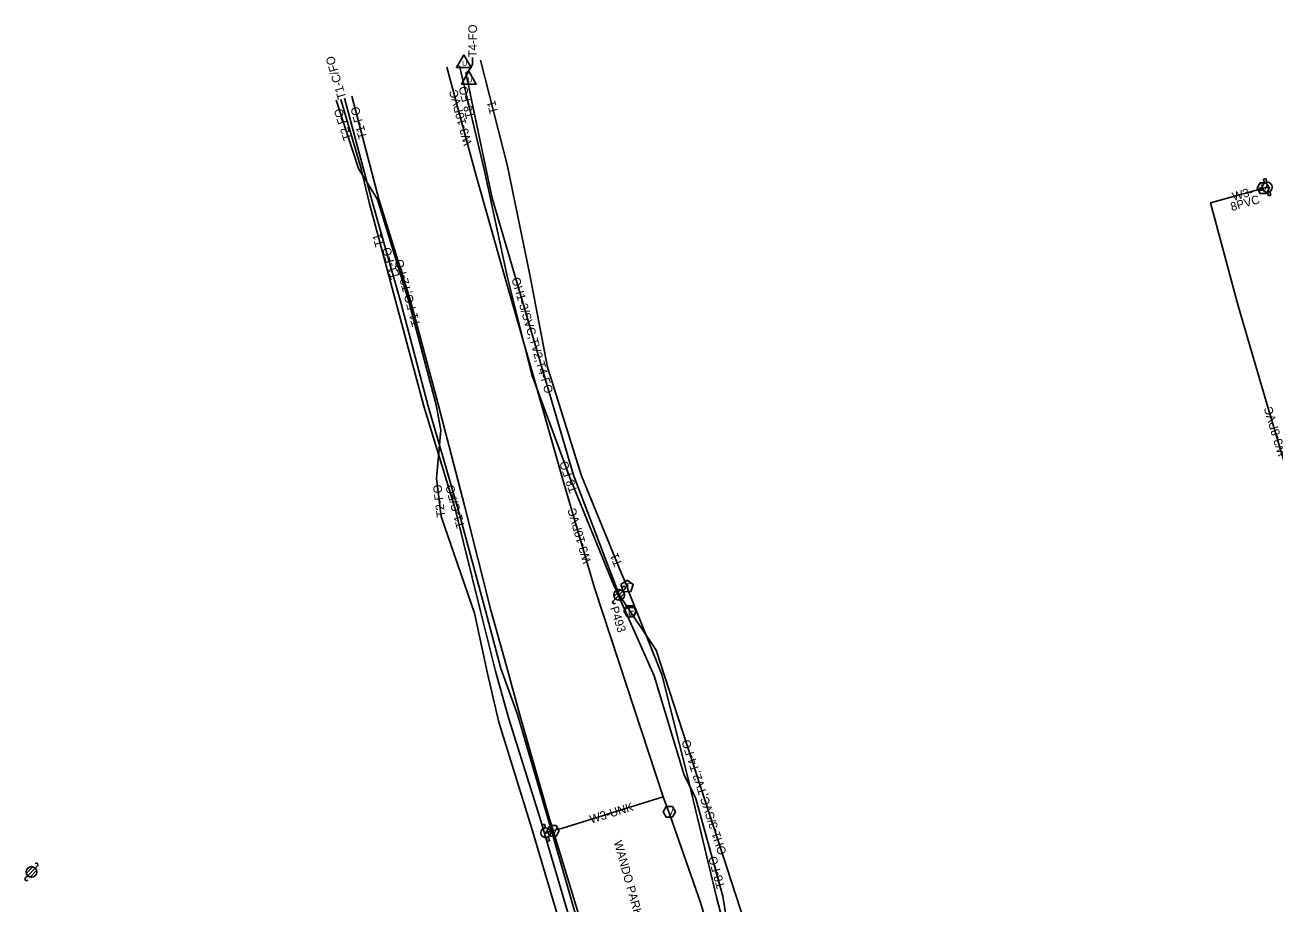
# Model space of a CAD drawing. Extents: x 2336688 to 2352634, y 362473 to 369571.
# Drawn here: x 2347665 to 2348251, y 367661 to 368073 of the extents above; entities that cross this region are included whole.
import ezdxf

# ---------------------------------------------------------------- set-up
doc = ezdxf.new("R2010")
doc.units = 0
for name, color, linetype in [('RD_EX_DV_TX_Prop', 7, 'Continuous'), ('RD_EX_RW', 7, 'Continuous'), ('RD_EX_RW_TX', 7, 'Continuous'), ('RD_HC_Data_Tic', 7, 'Continuous'), ('RD_PD_CstnLmt', 7, 'Continuous'), ('RD_PD_Final_TrvlWay', 7, 'Continuous'), ('RD_PD_PatLn3', 7, 'Continuous'), ('RD_PD_PatLn4', 7, 'Continuous'), ('RD_SHT_ShtClip', 7, 'Continuous'), ('RD_Sketch2', 7, 'Continuous'), ('RD_TX_Misc1', 7, 'Continuous')]:
    doc.layers.add(name, color=color, linetype=linetype)

msp = doc.modelspace()

# ---------------------------------------------------------------- linework, layer by layer
at = {"layer": 'RD_EX_RW_TX'}
for points in [[(2347874.49, 368058.09), (2347874.48, 368054.84), (2347872.37, 368051.57), (2347871.29, 368050.96)], [(2347868.44, 368054.11), (2347880, 368005.49), (2347890.68, 367955.5), (2347902.22, 367909.33), (2347920.64, 367859.94), (2347940.18, 367812), (2347959.68, 367768.1), (2347973.8, 367721.46), (2347979.06, 367711.04), (2347991.9, 367664.85), (2347998.75, 367622.27), (2348003.55, 367586.06), (2348009.9, 367584.2), (2348035.07, 367585.97), (2348081.85, 367595.07), (2348134.22, 367608.61), (2348182.28, 367613.21), (2348234.44, 367617.29), (2348281.25, 367627.74), (2348329.4, 367645.16), (2348376.54, 367659.65), (2348424.27, 367674.35), (2348472.98, 367689.81), (2348494.58, 367697.07)], [(2348009.29, 367585.15), (2348008.73, 367586.49), (2348008.27, 367587.28), (2347999.79, 367622.75), (2347989.04, 367663.67), (2347975.2, 367721.77), (2347963.24, 367768.72), (2347947.28, 367808.64), (2347947, 367810.06), (2347944.42, 367816.11), (2347925.56, 367861.98), (2347909.67, 367912.79), (2347901.3, 367956.19), (2347890.84, 368007.1), (2347878.18, 368056.88)], [(2347915.95, 367650.55), (2347902.14, 367697.01), (2347886.78, 367746.46), (2347881.45, 367769.17), (2347875.48, 367797.51), (2347859.7, 367842.81), (2347857.54, 367860.58), (2347859.66, 367883.25), (2347857.45, 367895.15), (2347844.53, 367943.62), (2347829.94, 367991.47), (2347821.02, 368006.02), (2347810.52, 368038.12)], [(2347939.95, 367565.03), (2347936.47, 367569.65), (2347934.13, 367571), (2347933.8, 367574.63), (2347934.6, 367589.64), (2347933.91, 367605.7), (2347920.61, 367652.29), (2347906.01, 367701.68), (2347891.44, 367747.98), (2347885.27, 367770.38), (2347878.23, 367798.4), (2347866.27, 367846.38), (2347851.57, 367894.63), (2347838.48, 367943.48), (2347825.98, 367990.01), (2347822.11, 368006.53), (2347812.66, 368038.44)], [(2347889.37, 367561.99), (2347894.01, 367562.08), (2347924.79, 367564.3), (2347941.5, 367567.41), (2347947.8, 367569.8), (2347937.61, 367605.85), (2347923.72, 367653.12), (2347909.59, 367702.05), (2347895.6, 367750), (2347887.81, 367771.63), (2347880.7, 367798.16), (2347867.71, 367846.16), (2347853.69, 367894.57), (2347840.87, 367943.17), (2347827.38, 367990.48), (2347814.45, 368038.97)], [(2347889.37, 367561.99), (2347894.01, 367563.28), (2347924.61, 367565.41), (2347935.34, 367567.38), (2347941.45, 367568.25), (2347948.79, 367570.76), (2347938.54, 367605.96), (2347925.1, 367653.38), (2347910.3, 367702.18), (2347896.52, 367750.26), (2347890.46, 367772.62), (2347883.06, 367798.99), (2347870.85, 367847.44), (2347858.32, 367895.46), (2347845.4, 367943.92), (2347830.6, 367991.62), (2347817.79, 368039.88)]]:
    msp.add_lwpolyline(points, dxfattribs=at)
msp.add_lwpolyline([(2347946.95, 367813), (2347944.12, 367810.89), (2347945.26, 367807.55), (2347948.79, 367807.6), (2347949.83, 367810.97)], close=True, dxfattribs=at)
at = {"layer": 'RD_HC_Data_Tic'}
for p, q in [((2347943.89, 367808.46), (2347940.83, 367805.4)), ((2347945.01, 367807.81), (2347941.48, 367804.28)), ((2347945.66, 367806.69), (2347942.6, 367803.63)), ((2347946.07, 367808.87), (2347945.01, 367807.81)), ((2347941.48, 367804.28), (2347940.42, 367803.21)), ((2347665.2, 367675.52), (2347668.26, 367678.58)), ((2347665.84, 367674.39), (2347669.38, 367677.93)), ((2347666.96, 367673.75), (2347670.03, 367676.81)), ((2347669.38, 367677.93), (2347670.44, 367678.99)), ((2347664.78, 367673.33), (2347665.84, 367674.39))]:
    msp.add_line(p, q, dxfattribs=at)
for centre in [(2347943.25, 367806.04), (2347667.61, 367676.16)]:
    msp.add_circle(centre, 2.5, dxfattribs=at)
for centre, start, end in [((2347945.54, 367809.4), 315, 135), ((2347940.95, 367802.68), 135, 315), ((2347669.91, 367679.52), 315, 135), ((2347665.31, 367672.8), 135, 315)]:
    msp.add_arc(centre, 0.75, start, end, dxfattribs=at)
at = {"layer": 'RD_PD_Final_TrvlWay'}
for points in [[(2347951.27, 367798.49), (2347949.8, 367800.97), (2347946.91, 367800.94), (2347945.5, 367798.43), (2347946.97, 367795.95), (2347949.85, 367795.98)], [(2347951.4, 367798.33), (2347949.95, 367800.83), (2347947.07, 367800.83), (2347945.62, 367798.33), (2347947.07, 367795.83), (2347949.95, 367795.83)]]:
    msp.add_lwpolyline(points, close=True, dxfattribs=at)
at = {"layer": 'RD_PD_PatLn3'}
for points in [[(2347870.39, 368059.36), (2347866.92, 368053.36), (2347873.85, 368053.36)], [(2347872.79, 368051.63), (2347869.33, 368045.63), (2347876.26, 368045.63)]]:
    msp.add_lwpolyline(points, close=True, dxfattribs=at)
at = {"layer": 'RD_SHT_ShtClip'}
for points in [[(2347871.29, 368050.96), (2347883.68, 367992.06), (2347921.81, 367862.28), (2347943.25, 367806.04)], [(2347943.25, 367806.04), (2347960.57, 367780.14), (2348012.56, 367620.55), (2348013.81, 367589.41)]]:
    msp.add_lwpolyline(points, dxfattribs=at)
at = {"layer": 'RD_Sketch2'}
for p, q in [((2348246.57, 368001.3), (2348245.47, 368000.97)), ((2348245.47, 368000.97), (2348246.01, 367999.19)), ((2348247.1, 367999.56), (2348246.57, 368001.3)), ((2348244.98, 367997.22), (2348243.54, 367996.78)), ((2348243.54, 367996.78), (2348243.88, 367995.68)), ((2348243.88, 367995.68), (2348245.29, 367996.1)), ((2348247.29, 367994.95), (2348247.82, 367993.23)), ((2348247.82, 367993.23), (2348248.92, 367993.56)), ((2348248.92, 367993.56), (2348248.41, 367995.24)), ((2347908.26, 367698.55), (2347907.15, 367698.22)), ((2347907.15, 367698.22), (2347907.66, 367696.54)), ((2347908.78, 367696.83), (2347908.26, 367698.55)), ((2347912.19, 367696.1), (2347910.79, 367695.68)), ((2347911.1, 367694.56), (2347912.53, 367695)), ((2347912.53, 367695), (2347912.19, 367696.1)), ((2347908.97, 367692.22), (2347909.5, 367690.48)), ((2347909.5, 367690.48), (2347910.6, 367690.81)), ((2347910.6, 367690.81), (2347910.06, 367692.59))]:
    msp.add_line(p, q, dxfattribs=at)
for points in [[(2347862.4, 368053.55), (2347875.72, 368004.38), (2347889.43, 367955.72), (2347903.08, 367908.55), (2347917.33, 367858.5), (2347931.68, 367809.35), (2347946.76, 367763.68), (2347963.93, 367711.37), (2347966.93, 367703.46), (2347981.46, 367661.87), (2347993.5, 367621.37), (2348001.18, 367589.64), (2348001.58, 367585.97), (2348009.43, 367561.67)], [(2348556.24, 367909.26), (2348552.57, 367908), (2348533.51, 367902.75), (2348495.8, 367890.75), (2348476.22, 367884.91), (2348498.22, 367806.14), (2348509.39, 367769.77), (2348452.39, 367753.96), (2348412.83, 367742.03), (2348383.64, 367733), (2348325.81, 367717.84), (2348294.09, 367735.62), (2348285.99, 367763.92), (2348272.89, 367808.65), (2348260.35, 367851.09), (2348247.19, 367895.19), (2348233.68, 367941.56), (2348220.7, 367989.93), (2348226.95, 367991.6), (2348244.37, 367996.56), (2348246.31, 367997.03), (2348247.28, 367997.26)], [(2347908.79, 367694.52), (2347910.17, 367694.9), (2347916.16, 367696.59), (2347963.93, 367711.37)]]:
    msp.add_lwpolyline(points, dxfattribs=at)
for points in [[(2348248.23, 367996.79), (2348246.78, 367999.29), (2348243.9, 367999.29), (2348242.45, 367996.79), (2348243.9, 367994.29), (2348246.78, 367994.29)], [(2347969.7, 367704.32), (2347968.25, 367706.82), (2347965.37, 367706.82), (2347963.92, 367704.32), (2347965.37, 367701.82), (2347968.25, 367701.82)], [(2347915.09, 367695.44), (2347913.65, 367697.94), (2347910.76, 367697.94), (2347909.32, 367695.44), (2347910.76, 367692.94), (2347913.65, 367692.94)]]:
    msp.add_lwpolyline(points, close=True, dxfattribs=at)
for centre, radius in [((2348247.28, 367997.26), 2.31), ((2348247.28, 367997.26), 0.289), ((2347908.79, 367694.52), 2.31), ((2347908.79, 367694.52), 0.289)]:
    msp.add_circle(centre, radius, dxfattribs=at)
for centre, start, end in [((2348247.28, 367997.26), 94.55198, 123.5283), ((2348247.28, 367997.26), 181.11252, 210.07976), ((2348247.28, 367997.26), 270.2057, 299.18202), ((2347908.79, 367694.52), 90.2057, 119.18202), ((2347908.79, 367694.52), 1.11252, 30.07976), ((2347908.79, 367694.52), 274.55198, 303.5283)]:
    msp.add_arc(centre, 2.31, start, end, dxfattribs=at)

# ---------------------------------------------------------------- texts
at = {"layer": 'RD_EX_DV_TX_Prop'}
msp.add_text('P493', height=4, rotation=288.04257, dxfattribs=at).set_placement((2347938.93, 367799.94))
at = {"layer": 'RD_EX_RW'}
for s, rotation, p in [('T4-FO', 89.82343, (2347876.49, 368058.12)), ('T1-C/FO', 106.49195, (2347815.26, 368039.19)), ('T8-FO', 103.37561, (2347875.39, 368029.95)), ('T1-FO', 104.87052, (2347825.01, 368020.49)), ('T1', 104.26618, (2347886.52, 368032.2)), ('T2-FO', 108.1109, (2347817.94, 368019.9)), ('T1', 105.03284, (2347832.86, 367969.9)), ('T1-FO', 105.91852, (2347840.06, 367954.66)), ('T1-FO,T2-FO', 104.91972, (2347850.06, 367932.54)), ('T8-FO', 108.82325, (2347923.85, 367854.67)), ('T2-FO', 96.92413, (2347861.73, 367842.7)), ('T1-C/FO', 105.13567, (2347870.98, 367837.99)), ('T1', 112.35318, (2347944.83, 367820.36)), ('T8-FO', 105.53582, (2347992.97, 367669.05))]:
    msp.add_text(s, height=4, rotation=rotation, dxfattribs=at).set_placement(p)
at = {"layer": 'RD_EX_RW_TX'}
msp.add_text('T', height=3.75, rotation=0.77933, dxfattribs=at).set_placement((2347945.79, 367807.76))
at = {"layer": 'RD_PD_CstnLmt'}
for s, rotation, p in [('W3-10PVC', 105.14819, (2347874.23, 368017.51)), ('8PVC', 15.89716, (2348230.63, 367986)), ('W3-', 15.89716, (2348231.47, 367990.81)), ('W3-8PVC', 106.611, (2348256.19, 367872.02)), ('W3-10PVC', 106.04487, (2347930.16, 367821.5)), ('W3-UNK', 17.18765, (2347930.11, 367698.81))]:
    msp.add_text(s, height=4, rotation=rotation, dxfattribs=at).set_placement(p)
at = {"layer": 'RD_PD_Final_TrvlWay'}
msp.add_text('E', height=3.75, rotation=0.59549, dxfattribs=at).set_placement((2347947.27, 367796.57))
msp.add_text('E', height=3.75, dxfattribs=at).set_placement((2347947.37, 367796.46))
at = {"layer": 'RD_PD_PatLn3'}
for p in [(2347869.63, 368054.16), (2347872.04, 368046.43)]:
    msp.add_text('U', height=2.4, dxfattribs=at).set_placement(p)
at = {"layer": 'RD_PD_PatLn4'}
for rotation, p in [(286.37266, (2347892.68, 367954.33)), (108.04257, (2347993.68, 367684.97))]:
    msp.add_text('OH1-3/SVC,TV2,T4-FO', height=4, rotation=rotation, dxfattribs=at).set_placement(p)
at = {"layer": 'RD_Sketch2'}
for p in [(2348244.13, 367994.92), (2347965.6, 367702.45), (2347911, 367693.57)]:
    msp.add_text('V', height=3.75, dxfattribs=at).set_placement(p)
at = {"layer": 'RD_TX_Misc1'}
msp.add_text('WANDO PARK BLVD', height=4, rotation=285.5754, dxfattribs=at).set_placement((2347940.68, 367690.26))

doc.saveas('drawing.dxf')
